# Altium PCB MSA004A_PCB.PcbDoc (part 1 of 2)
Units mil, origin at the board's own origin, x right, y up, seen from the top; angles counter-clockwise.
Board outline 2300 x 2720 mil, 2 copper layers (Top Layer, Bottom Layer), stack 62 mil thick; 117 components, 85 nets, 350 pads, 179 vias.
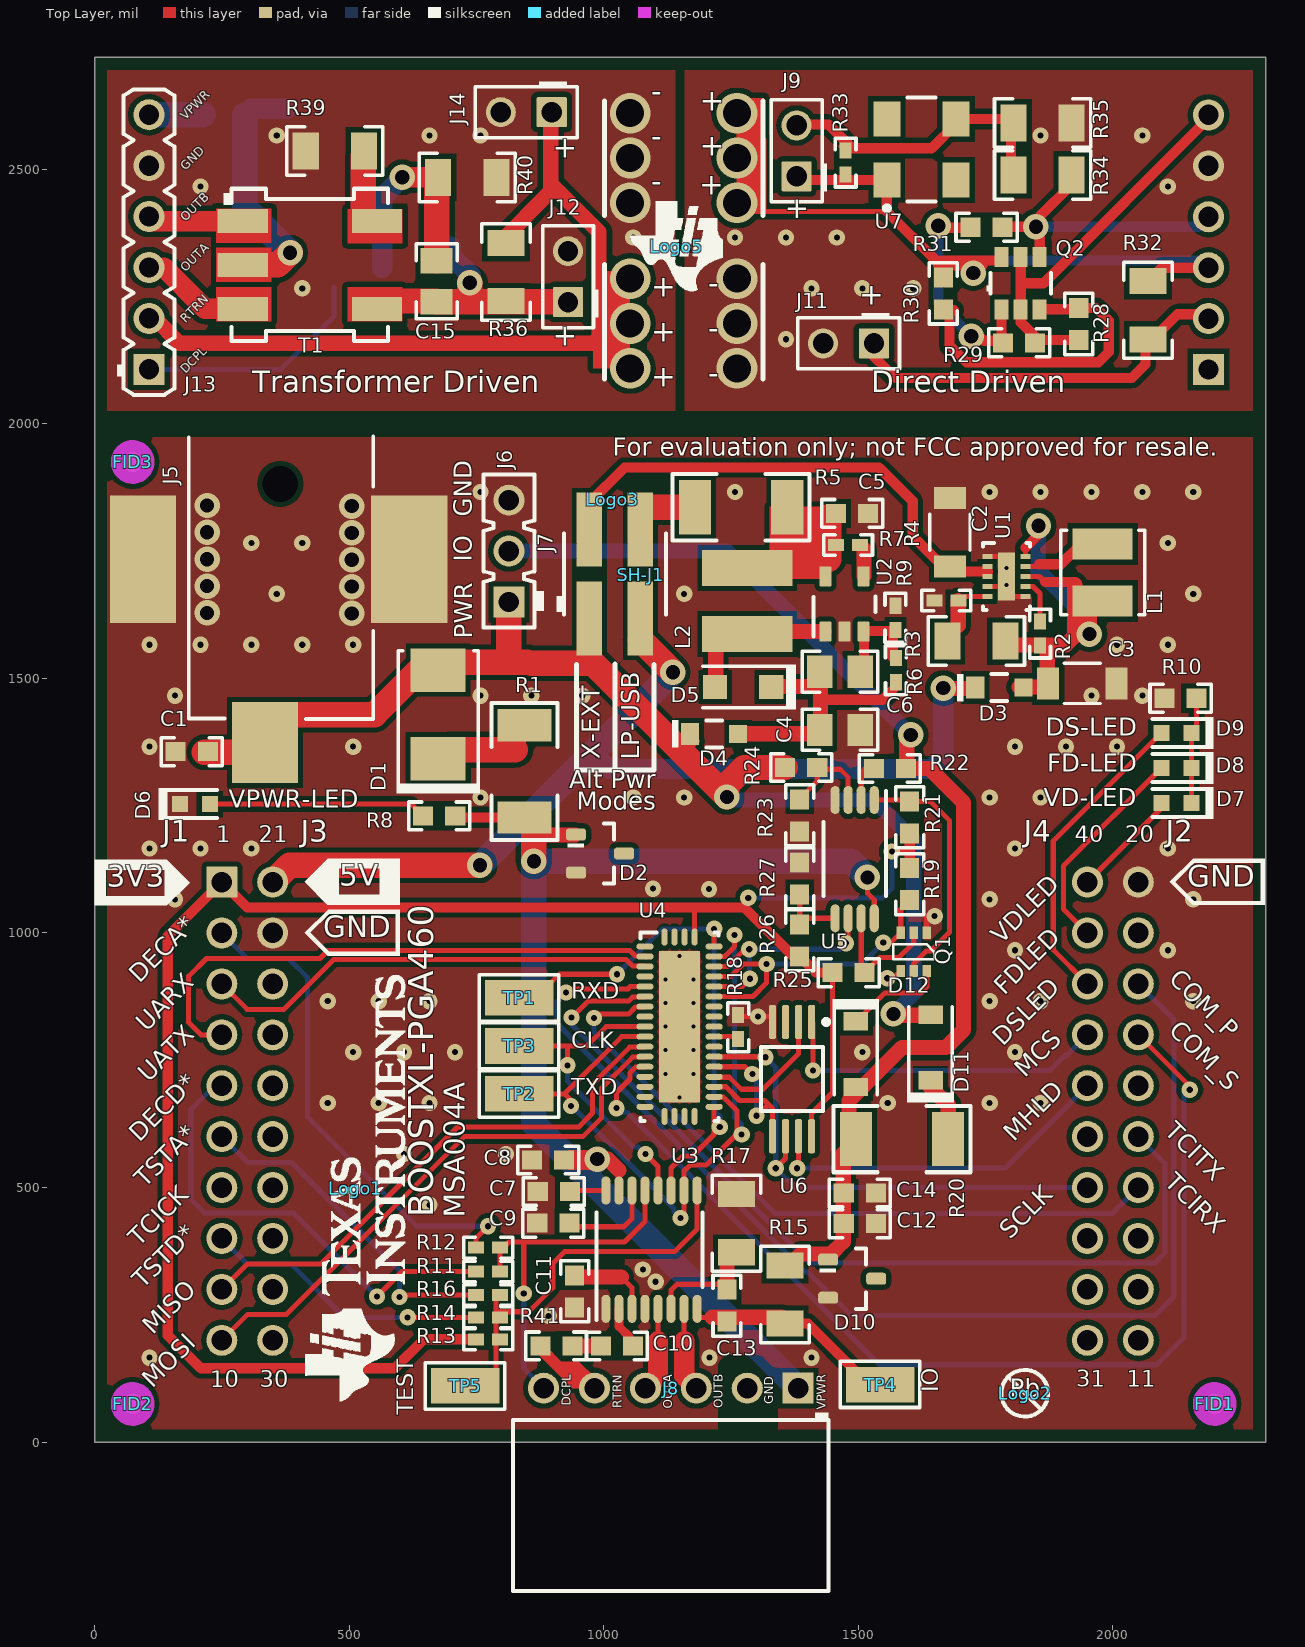
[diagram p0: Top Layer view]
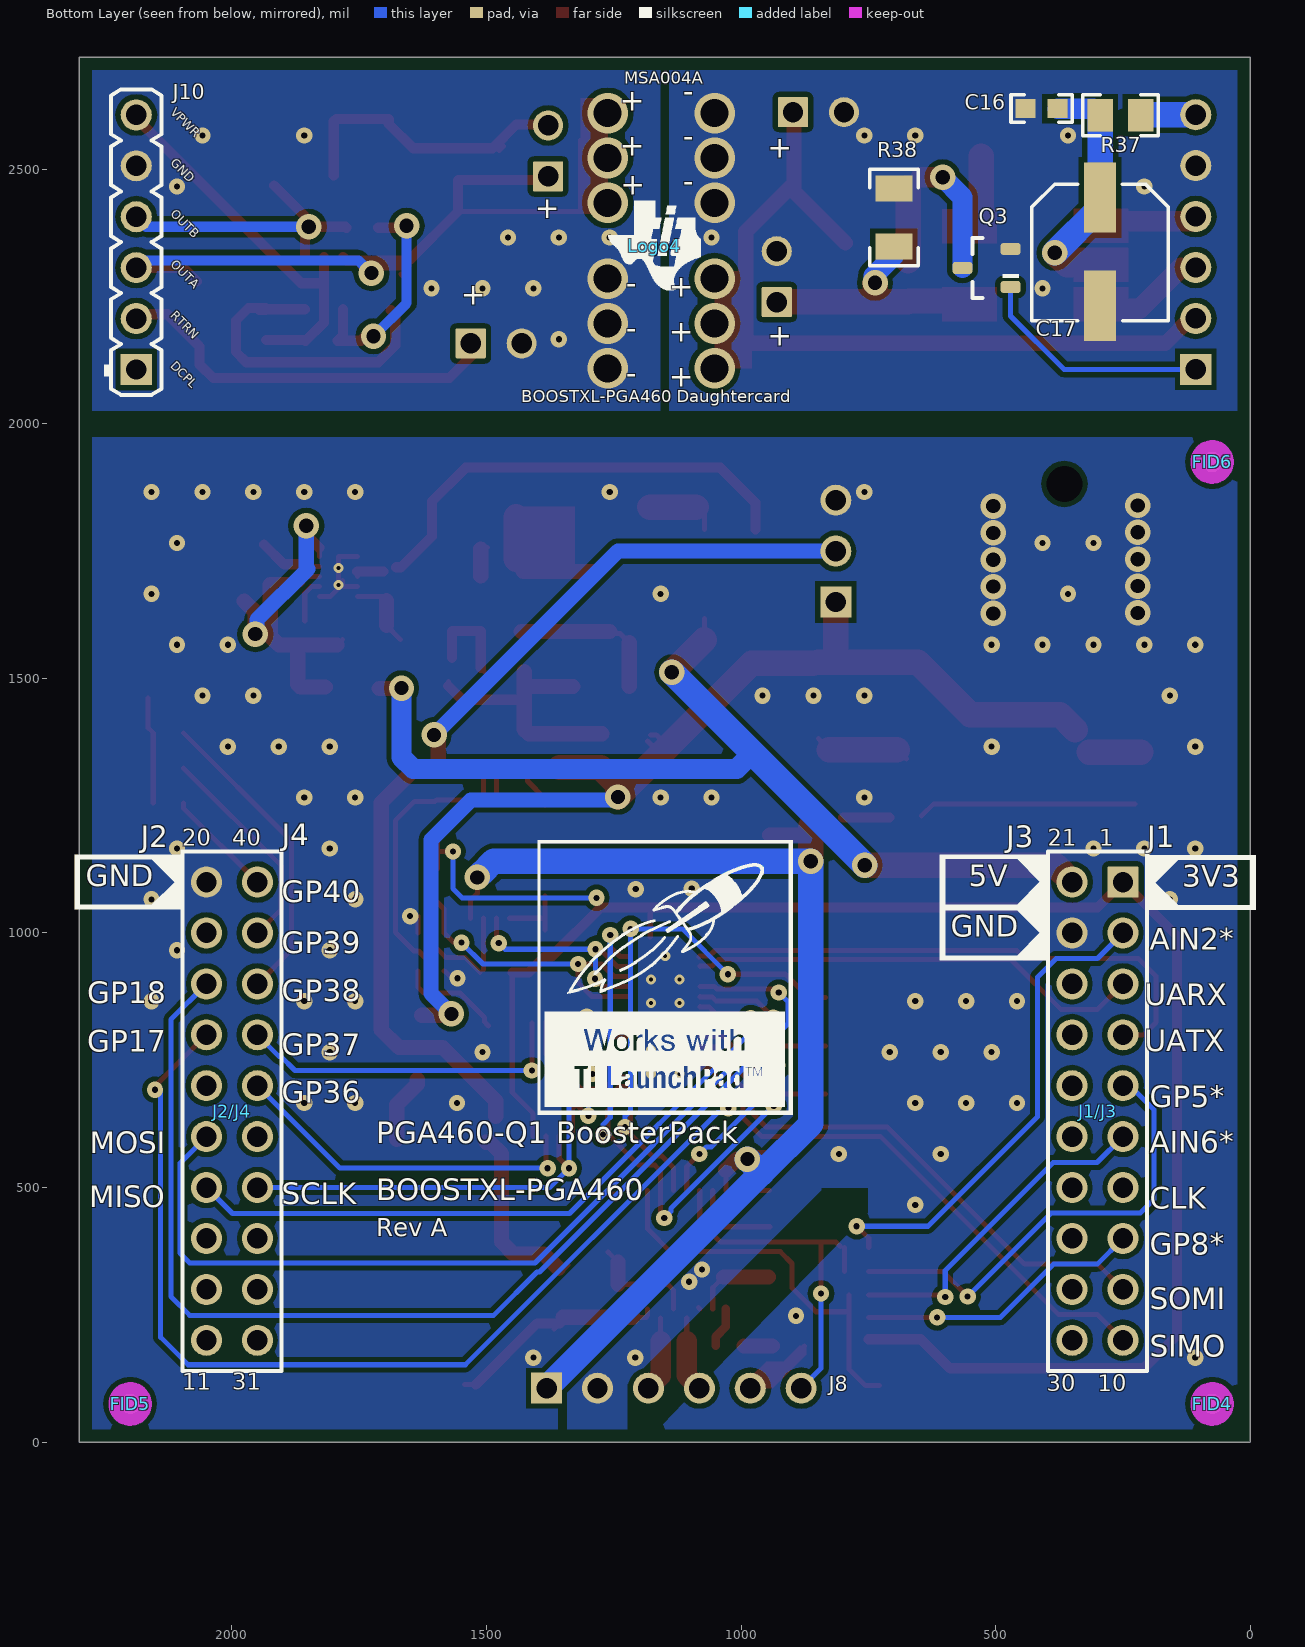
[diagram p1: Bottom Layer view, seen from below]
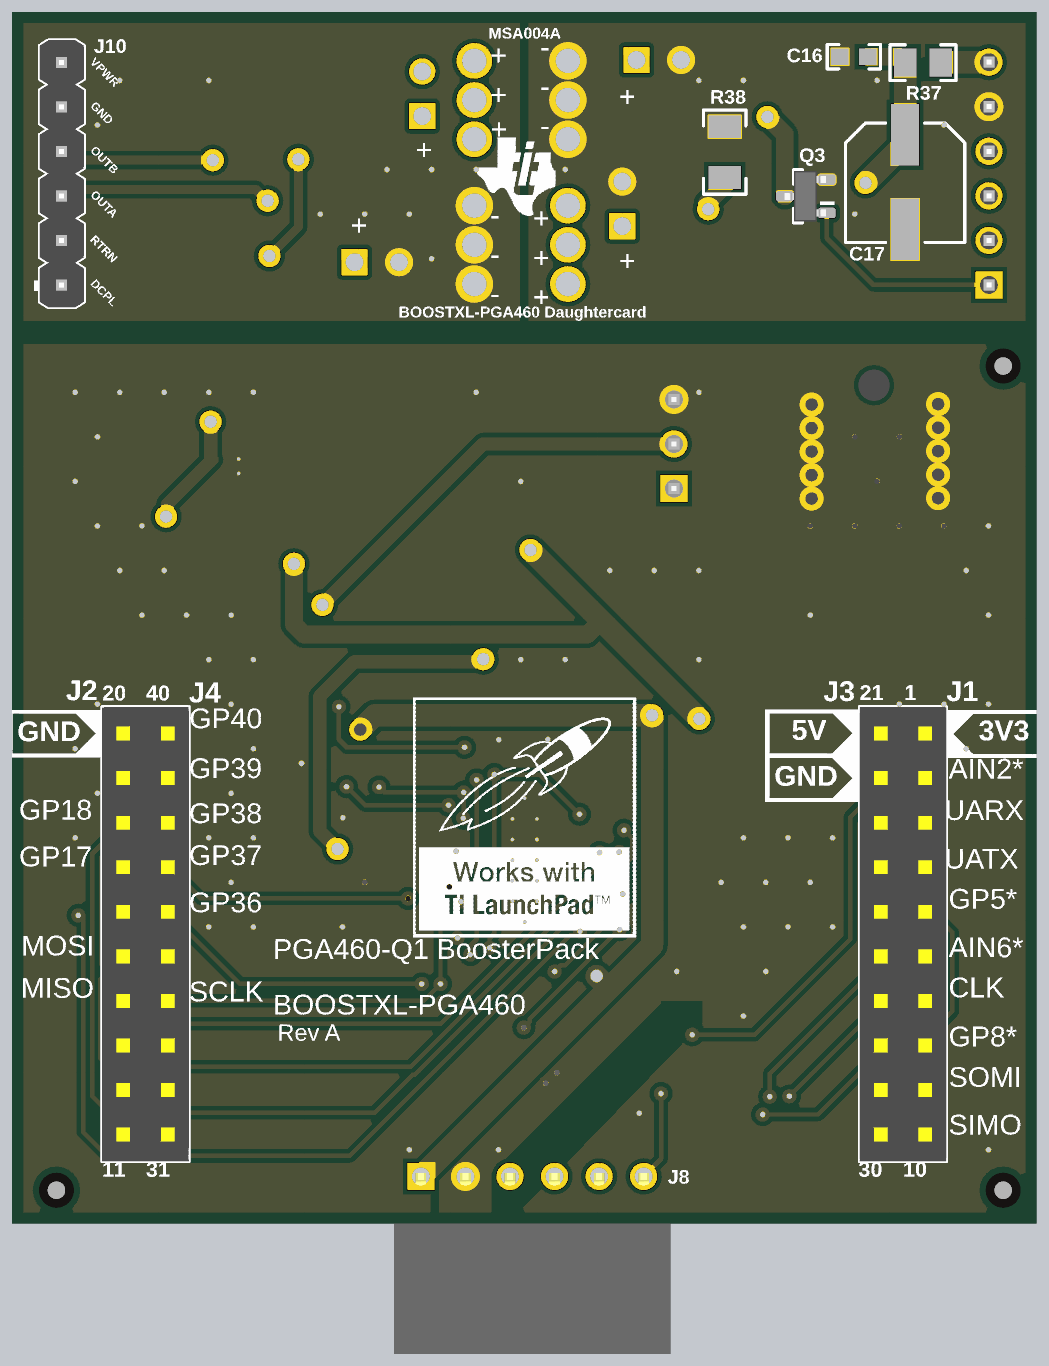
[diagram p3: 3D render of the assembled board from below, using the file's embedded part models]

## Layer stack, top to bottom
Top Solder: solder mask 0.4, Solder Resist, Dk 3.5
Top Layer: signal copper 1.4
Dielectric1: core 59.2, FR-4, Dk 4.8
Bottom Layer: signal copper 1.4
Bottom Solder: solder mask 0.4, Solder Resist, Dk 3.5

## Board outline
0,0 2300,0 2300,2720 0,2720
board region "Layer Stack Region 1": 0,2000 0,2720 2300,2720 2300,2000
board region "Layer Stack Region 1": 2300,2000 2300,0 0,0 0,2000

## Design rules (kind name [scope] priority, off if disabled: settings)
AcuteAngle [All] p1: minimum=4.50000000000000E+0001 checktracksonly=FALSE
AssemblyTestPointUsage [All] p1: valid=2
BoardOutlineClearance BoardOutlineClearance_MountingHoles [OnCopper and InComponentClass('Mounting Holes')] p1: gap=25
BoardOutlineClearance BoardOutlineClearance_Poly [OnCopper and IsPoly] p2: gap=25
BoardOutlineClearance [OnCopper and Not InComponentClass('Logo') and not InComponentClass('FiducialMark') and not InRegion(1000,500,4000,800) and not InPoly] p3: gap=25
Clearance Clearance_6 [InNamedPolygon('Top-GNDD')] p1: gap=10
Clearance Clearance_5 [InNamedPolygon('Btm-GNDX')] p2: gap=10
Clearance Clearance_4 [InNamedPolygon('Top-GNDX')] p3: gap=10
Clearance Clearance_3 [InNamedPolygon('Btm-GNDD')] p4: gap=10
Clearance Clearance_2 [InNamedPolygon('Top-GND')] p5: gap=10
Clearance Clearance_1 [InNamedPolygon('Btm-GND')] p6: gap=10
Clearance Clearance_Keepouts [((IsTrack Or IsArc) And Not InPoly) And IsFree and IsKeepOut vs ((IsTrack Or IsArc) And Not InPoly) And IsFree and IsKeepOut] p7: gap=0
Clearance Clearance_Poly [InPolygon] p8: gap=25
Clearance [All] p9: gap=7.87
ComponentClearance ComponentClearance_1 [All] p1: gap=10 collisioncheckmode=3 verticalgap=10 showdistances=FALSE
ComponentClearance ComponentClearance_MountingHoles_FiducialMarks [InComponentClass('Mounting Holes') vs InComponentClass('FiducialMark')] p2: gap=50 collisioncheckmode=3 verticalgap=10 showdistances=FALSE
ComponentClearance ComponentClearance_Shunt [InComponentClass('Header') vs InComponentClass('Shunt');] p3: gap=0 collisioncheckmode=3 verticalgap=0 showdistances=FALSE
ComponentClearance ComponentClearance_Logo [InComponentClass('Logo')] p4: gap=50 collisioncheckmode=3 verticalgap=10 showdistances=FALSE
ComponentClearance ComponentClearance_ScrewToNut [(HasFootprint('NY PMS 440 0025 PH')) vs (HasFootprint('Keystone_1902C'))] p5: gap=5 collisioncheckmode=3 verticalgap=10 showdistances=FALSE
ComponentClearance ComponentClearance_MountingHoles [InComponentClass('Mounting Holes')] p6: gap=250 collisioncheckmode=3 verticalgap=100000 showdistances=FALSE
ComponentClearance ComponentClearance_SmallPassives [HasFootprint('0201*') or HasFootprint('0402*') or HasFootprint('0508') or HasFootprint('0603*') or HasFootprint('0612') or HasFootprint('0805*') or HasFootprint('0815*') or HasFootprint('0830*') or HasFootprint('1206*') or HasFootprint('1210*') or HasFootprint('1808*') or HasFootprint('1812*') or HasFootprint('1825*') or HasFootprint('2010*') or HasFootprint('2220*') or HasFootprint('2225*') or HasFootprint('2512*') or HasFootprint('2728*') or HasFootprint('3518*') vs HasFootprint('0201*') or HasFootprint('0402*') or HasFootprint('0508') or HasFootprint('0603*') or HasFootprint('0612') or HasFootprint('0805*') or HasFootprint('0815*') or HasFootprint('0830*') or HasFootprint('1206*') or HasFootprint('1210*') or HasFootprint('1808*') or HasFootprint('1812*') or HasFootprint('1825*') or HasFootprint('2010*') or HasFootprint('2220*') or HasFootprint('2225*') or HasFootprint('2512*') or HasFootprint('2728*') or HasFootprint('3518*')] p7: gap=14.96 collisioncheckmode=3 verticalgap=10 showdistances=FALSE
ComponentClearance ComponentClearance_THtoSMT [IsThruComponent vs IsSMTComponent] p8: gap=40 collisioncheckmode=3 verticalgap=30 showdistances=FALSE
ComponentClearance ComponentClearance_THtoTH [IsThruComponent vs IsThruComponent] p9: gap=30 collisioncheckmode=3 verticalgap=30 showdistances=FALSE
DiffPairsRouting [All] p1: maxlimit=100 minlimit=10 mostfreqgap=10 toplayer_minwidth=15 toplayer_maxwidth=15 toplayer_prefwidth=15 bottomlayer_minwidth=15 bottomlayer_maxwidth=15 bottomlayer_prefwidth=15 maxuncoupledlength=1000
FabricationTestPointUsage TestPointUsage [All] p1: valid=2 allowmultiple=FALSE
FabricationTestpoint Testpoint [All] p1: side=3 testpointundercomponent=TRUE minsize=40 maxsize=100 preferedsize=60 minholesize=0 maxholesize=40 preferedholesize=32 testpointgrid=1 allowsidetop=TRUE allowsidebottom=TRUE usegrid=TRUE gridtolerance=0.01
FanoutControl Fanout_LCC [IsLCC] p1: bgadir=Out bgaviamode=Centered fanoutstyle=Auto fanoutdirection=Alternating viagrid=1 // Fanout_LCC (Default Rule)
FanoutControl Fanout_BGA [IsBGA] p2: bgadir=Out bgaviamode=Centered fanoutstyle=Auto fanoutdirection=Alternating viagrid=1 // Fanout_BGA (Default Rule)
FanoutControl Fanout_Default [All] p4: bgadir=Out bgaviamode=Centered fanoutstyle=Auto fanoutdirection=Alternating viagrid=1 // Fanout_Default (Default Rule)
FanoutControl Fanout_Small [(CompPinCount < 5)] p5: bgadir=Out bgaviamode=Centered fanoutstyle=Auto fanoutdirection=OutThenIn viagrid=1 // Fanout_Small (Default Rule)
HoleSize [All] p1: absolutevalues=TRUE maxlimit=251 minlimit=7.87 maxpercent=80.000 minpercent=20.000
MinimumAnnularRing MinimumAnnularRing_ThermalPadVias [IsVia and InAnyComponent] p1: minimumring=5.91
MinimumAnnularRing [All] p2: minimumring=8
MinimumSolderMaskSliver MinimumSolderMaskSliver_Logo [InComponentClass('Logo') vs InComponentClass('Logo')] p1: minsoldermaskwidth=0.7
MinimumSolderMaskSliver [All] p2: minsoldermaskwidth=3.94
PlaneConnect [All] p1: planeconnectstyle=Relief reliefexpansion=10 reliefentries=4 reliefconductorwidth=10 reliefairgap=10
PolygonConnect PolygonConnect_6 [All vs IsNamedPolygon('Top-GNDD')] p1: connectstyle=Direct reliefconductorwidth=10 reliefentries=4 polygonreliefangle="90 Angle" airgapwidth=10
PolygonConnect PolygonConnect_5 [All vs IsNamedPolygon('Top-GNDX')] p2: connectstyle=Direct reliefconductorwidth=10 reliefentries=4 polygonreliefangle="90 Angle" airgapwidth=10
PolygonConnect PolygonConnect_4 [All vs IsNamedPolygon('Btm-GNDD')] p3: connectstyle=Direct reliefconductorwidth=10 reliefentries=4 polygonreliefangle="90 Angle" airgapwidth=10
PolygonConnect PolygonConnect_3 [All vs IsNamedPolygon('Btm-GNDX')] p4: connectstyle=Direct reliefconductorwidth=10 reliefentries=4 polygonreliefangle="90 Angle" airgapwidth=10
PolygonConnect PolygonConnect_2 [All vs IsNamedPolygon('Btm-GND')] p5: connectstyle=Direct reliefconductorwidth=10 reliefentries=4 polygonreliefangle="90 Angle" airgapwidth=10
PolygonConnect PolygonConnect_1 [All vs IsNamedPolygon('Top-GND')] p6: connectstyle=Direct reliefconductorwidth=10 reliefentries=4 polygonreliefangle="90 Angle" airgapwidth=10
PolygonConnect [All] p7: connectstyle=Relief reliefconductorwidth=10 reliefentries=4 polygonreliefangle="90 Angle" airgapwidth=10
RoutingVias ThermalPadVias [IsVia and InAnyComponent] p1: holewidth=7.87 width=19.68 viastyle="Through Hole" minholewidth=7.87 minwidth=19.68 maxholewidth=12.99 maxwidth=23.62
RoutingVias [All] p2: holewidth=16 width=34 viastyle="Through Hole" minholewidth=7.87 minwidth=26 maxholewidth=40 maxwidth=65
SilkToBoardRegionClearance [Not ((IsComment or IsDesignator) And (Hide <> 'False')) and not InRegion(1000,500,4000,800)] p1:
SilkToSilkClearance SilkToSilkClearance_Pb-FreeLogo [(HasFootprint('Pb-Free_Overlay_Medium') OR HasFootprint('Pb-Free_Overlay_Small')) vs (HasFootprint('Pb-Free_Overlay_Medium') OR HasFootprint('Pb-Free_Overlay_Small'))] p1: silktosilkclearance=0
SilkToSilkClearance [All] p2: silktosilkclearance=4
SilkToSolderMaskClearance SilkToComponentPadClearance [IsPad and InAnycomponent] p1: minsilkscreentomaskgap=5 clearancetoexposedcopper=TRUE
SilkToSolderMaskClearance "Silk to Solder Mask Opening" [All] p2: minsilkscreentomaskgap=4 clearancetoexposedcopper=FALSE
SolderMaskExpansion [All] p1: expansion=1.97
Width [All] p1: maxlimit=100 minlimit=6 preferedwidth=10 checkconnectedcopper=TRUE
15 further rules are at their usual default settings.

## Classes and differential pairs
component class Logo: Logo1 Logo4 Logo5
component class MSA004A_HW: FID1 FID2 FID3 FID4 FID5 FID6 Logo1 Logo2 Logo3 Logo4 Logo5 SH-J1 ZZ1 ZZ2 ZZ3 ZZ4 ZZ5
component class FiducialMark: FID1 FID2 FID3 FID4 FID5 FID6
component class AssemblyNote: ZZ1 ZZ2 ZZ3 ZZ4 ZZ5
component class Header: J6 J7 J9 J10 J11 J12 J13 J14
component class MSA004A_USSC: C7 C8 C9 C10 C11 C12 C13 C14 D10 D11 D12 J1/J3 J2/J4 J8 Q1 R11 R12 R13 R14 R15 R16 R17 R18 R19 R20 R21 R22 R23 R24 R25 R26 R27 R41 TP1 TP2 TP3 TP4 TP5 U3 U4 U5 U6
component class MSA004A_XDCR: C15 C16 C17 H1 J9 J10 J11 J12 J13 J14 Q2 Q3 R28 R29 R30 R31 R32 R33 R34 R35 R36 R37 R38 R39 R40 T1 U7
component class MSA004A_PWR: C1 C2 C3 C4 C5 C6 D1 D2 D3 D4 D5 D6 D7 D8 D9 J5 J6 J7 L1 L2 R1 R2 R3 R4 R5 R6 R7 R8 R9 R10 U1 U2

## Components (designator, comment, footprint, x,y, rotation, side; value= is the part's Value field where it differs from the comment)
C1 "C1608X5R1H474K080AB" 0603 191,1356 r180 top
C2 "GRM31CR71H225KA88L" 1206_180 1680,1787 r90 top
C3 "GRM31CR61A226KE19L" 1206_180 1940,1490 r0 top
C4 "GRM21BR61C106KE15L" 0805_HV 1464,1399 r0 top
C5 "GRM188R61A475MAAJ" 0603 1488,1824 r0 top
C6 "CC0805KRX7R9BB102" 0805_HV 1464,1513 r0 top
C7 "C1608X7R1H104K080AA" 0603 902,492 r180 top
C8 "C1608X7R1H104K080AA" 0603 891,554 r180 top
C9 "C1608X7R1H104K080AA" 0603 901,430 r180 top
C10 "GRM1885C2A391JA01D" 0603 1026,189 r180 top
C11 "GRM188R71H333KA61D" 0603 943,296 r270 top
C12 "C1608X7R1H104K080AA" 0603 1503,429 r0 top
C13 "C1608X7R1H104K080AA" 0603 1242,268 r90 top
C14 "C0603C221K5RACTU" 0603 1503,489 r0 top
C15 "GRM2165C2A152JA01D" 0805_HV 672,2280 r90 top
C16 "C1608X7R1H104K080AA" 0603 410,2619 r180 bottom
C17 "EMVA350ADA101MF80G" CAPSMT_62_F80 295,2338 r270 bottom
D1 "B260-13-F" SMB 675,1429 r90 top
D2 "SZMMBZ27VCLT1G" SOT-23 993,1156 r0 top
D3 "DB2130200L" SMini2-F5-B 1777,1482 r0 top
D4 "DB2130200L" SMini2-F5-B 1217,1391 r0 top
D5 "PMEG6010CEH,115" SOD-123F 1274,1483 r180 top
D6 "LTST-C191KFKT" LTST-C191_Orange 197,1253 r180 top
D7 "LTST-C191KRKT" LTST-C191_Red 2125,1255 r0 top
D8 "LTST-C191KRKT" LTST-C191_Red 2125,1324 r0 top
D9 "LTST-C191KRKT" LTST-C191_Red 2125.03,1392.97 r0 top
D10 "SZMMBZ27VCLT1G" SOT-23 1488,321 r0 top
D11 "BAV3004W-7-F" SOD-123 1642,775 r90 top
D12 "BAV3004W-7-F" SOD-123 1495,762 r270 top
FID1 "Fiducial" Fiducial10-20 2200,75 r0 top
FID2 "Fiducial" Fiducial10-20 75,75 r0 top
FID3 "Fiducial" Fiducial10-20 75,1925 r0 top
FID4 "Fiducial" Fiducial10-20 75,75 r180 bottom
FID5 "Fiducial" Fiducial10-20 2200,75 r180 bottom
FID6 "Fiducial" Fiducial10-20 75,1925 r180 bottom
J1/J3 "SSQ-110-03-T-D" BoosterPack_40pin_J1J3 300,650 r180 bottom locked
J2/J4 "SSQ-110-03-T-D" BoosterPack_40pin_J2J4 2000,650 r180 bottom locked
J5 "RASM712PX" Switchcraft_RASM712PX 365,2000 r180 top
J6 "TSW-103-07-T-S" Samtec_TSW-103-07-T-S 814,1750 r90 top
J7 "0015912040" Molex_0015912040 1022,1705 r90 top
J8 "PPPC061LGBN-RC" Sullins_xPxC061LGBN 1132,106 r270 top
J9 "PEC02SAAN" CONN_PEC02SAAN 1379,2536 r90 top
J10 "PBC06SAAN" Sullins_PxC06SAAN 2187.95,2356.62 r90 bottom
J11 "PEC02SAAN" CONN_PEC02SAAN 1481,2158 r180 top
J12 "PEC02SAAN" CONN_PEC02SAAN 930,2289 r90 top
J13 "PBC06SAAN" Sullins_PxC06SAAN 107.05,2357 r90 top
J14 "PEC02SAAN" CONN_PEC02SAAN 848,2612 r180 top
L1 "LQH44PN100MP0L" IND_LQH44P 1980,1708 r270 top
L2 "SDR0403-100ML" SDR0403 1282,1652 r270 top
Logo1 "Texas Instruments" TI_Stacked_Overlay_Small 512,499 r90 top
Logo2 "Pb-Free Symbol" Pb-Free_Overlay_Small 1827,96 r0 top
Logo3 "FCC disclaimer" FCC_disclaimer 1017,1852 r0 top
Logo4 "Texas Instruments" TI_Symbol_Overlay_Small 1170.12,2349.78 r180 bottom
Logo5 "Texas Instruments" TI_Symbol_Overlay_Small 1142.74,2348.5 r0 top
Q1 "2N7002DW" SOT-363 1609,963 r270 top
Q2 "FDC6506P" superSOT-6 1819,2276 r90 top
Q3 "BSS123" SOT-23 518,2306 r0 bottom
R1 "CRCW201010R0JNEF" 2010 844.56,1317.46 r270 top
R2 "CRCW0402100KFKED" 0402 1857,1588 r90 top
R3 "RC1206FR-072M2L" 1206 1732,1573 r0 top
R4 "CRCW0402383KFKED" 0402 1673,1653 r180 top
R5 "CRCW201033R0JNEF" 2010 1270,1836 r0 top
R6 "CRCW040251K1FKED" 0402 1574,1516 r270 top
R7 "CRCW040210K0FKED" 0402 1480,1762 r0 top
R8 "RC0603JR-0751KL" 0603 677,1230 r180 top
R9 "CRCW040210K0FKED" 0402 1573,1619 r90 top
R10 "RC0603JR-0710KL" 0603 2133,1461 r180 top
R11 "CRCW04020000Z0ED" 0402 773,335 r180 top
R12 "CRCW04020000Z0ED" 0402 773,382 r180 top
R13 "CRCW0402100KJNED" 0402 773,201.79 r180 top
R14 "CRCW04020000Z0ED" 0402 773,245 r180 top
R15 "CRCW12060000Z0EA" 1206 1356,290 r270 top
R16 "CRCW04020000Z0ED" 0402 773,289 r180 top
R17 "CRCW12060000Z0EA" 1206 1261,430 r270 top
R18 "CRCW040210K0FKED" 0402 1264,815 r90 top
R19 "CRCW06031K00JNEA" 0603 1601,1096 r270 top
R20 "CRCW20101K00JNEF" 2010 1586,595 r0 top
R21 "CRCW06031K00JNEA" 0603 1601,1227 r270 top
R22 "CRCW0603100KJNEA" 0603 1562,1323 r0 top
R23 "CRCW0603100KJNEA" 0603 1385,1231 r90 top
R24 "CRCW0603100KJNEA" 0603 1388,1325 r180 top
R25 "CRCW06031K00JNEA" 0603 1481,922 r180 top
R26 "CRCW0603100KJNEA" 0603 1385,985.5 r90 top
R27 "CRCW0603100KJNEA" 0603 1385,1107 r270 top
R28 "CRCW06031K00JNEA" 0603 1933,2196 r270 top
R29 "CRCW06031K00JNEA" 0603 1816,2159 r0 top
R30 "CRCW06031K00JNEA" 0603 1667,2256 r90 top
R31 "CRCW06031K00JNEA" 0603 1752,2386 r0 top
R32 "CRCW12060000Z0EA" 1206 2069,2223 r270 top
R33 "CRCW04022K00JNED" 0402 1475,2513 r270 top
R34 "CRCW12060000Z0EA" 1206 1862,2489 r180 top
R35 "CRCW12060000Z0EA" 1206 1862,2591 r180 top
R36 "CRCW12060000Z0EA" 1206 808,2298 r90 top
R37 "CRCW0805100RJNEA" 0805_HV 255,2606 r0 bottom
R38 "CRCW12062K70JNEA" 1206 700,2405 r270 bottom
R39 "CRCW12060000Z0EA" 1206 472,2536 r0 top
R40 "CRCW12060000Z0EA" 1206 732,2484 r180 top
R41 "CRCW0603100RFKEA" 0603 907,189 r0 top
SH-J1 "60900213421" Wurth_60900213421 1073,1704 r90 top
T1 "B78416A2232A003" TDK_B78416A2232A003 423,2312 r0 top
TP1 "RXD" Testpoint_Keystone_Miniature 834,873 r0 top
TP2 "TXD" Testpoint_Keystone_Miniature 834,684 r0 top
TP3 "CLK" Testpoint_Keystone_Miniature 834,778 r180 top
TP4 "IO" Testpoint_Keystone_Miniature 1543,113 r180 top
TP5 "TEST" Testpoint_Keystone_Miniature 728,111 r0 top
U1 "TPS62175DQCR" DQC0010A 1791,1700 r0 top
U2 "LMR62421XMFX/NOPB" DBV0005A_N 1473,1646 r90 top
U3 "PGA460TPWRQ1" PW0016A_N 1094,378 r90 top
U4 "TS3L501ERUAR" RUA0042A 1149,816 r0 top
U5 "LM2903PW" PW0008A_N 1493,1145 r270 top
U6 "23LC512-I/ST" TSSOP-8 1370,713 r270 top
U7 "MA40H1S-R" MA40H1S 1624,2538.62 r90 top
ZZ1 "These assemblies are ESD sensitive, ESD precautions shall be observed." AssemblyNote 185,3829.11 r0 top
ZZ2 "These assemblies must be clean and free from flux and all contaminants. Use of no clean flux is not acceptable." AssemblyNote 185,3740.56 r0 top
ZZ3 "These assemblies must comply with workmanship standards IPC-A-610 Class 2, unless otherwise specified." AssemblyNote 185,3652 r0 top
ZZ4 "Add score line between boards for separation post-assembly." AssemblyNote 185,3528 r0 top
ZZ5 "Connect MA58MF14-7N (H1) XDCR to J12 holes. Black wired pin must be connected to GND_XD (-)." AssemblyNote 185,3448 r0 top

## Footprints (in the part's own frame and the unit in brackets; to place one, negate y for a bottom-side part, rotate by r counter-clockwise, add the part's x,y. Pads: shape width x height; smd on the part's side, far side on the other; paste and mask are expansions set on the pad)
0402 [mm] "0402 from SM-752 data"
  rect 0.8x0.6 smd: 1(-0.6,0) 2(0.6,0)
  silkscreen extent -1.22,-0.52 1.22,0.52, body extent -0.55,-0.3 0.55,0.3, height 0.6
0603 [mm] "0603 from SM-752 data"
  rect 1x0.95 smd: 1(-0.8,0) 2(0.8,0)
  silkscreen extent -1.52,-0.69 1.52,0.69, body extent -0.87,-0.47 0.87,0.47, height 1
0805_HV [mil] "0805 with 30mil clearance between pads"
  rect 50x63 smd: 1(-40,0) 2(40,0)
  silkscreen extent -74,-40 74,40, body extent -43,-29 43,29, height 57
1206 [mm] "1206 from SM-752 data"
  rect 1.3x1.85 smd: 1(-1.45,0) 2(1.45,0)
  silkscreen extent -2.4,-1.21 2.4,1.21, body extent -1.7,-0.9 1.7,0.9, height 1.35
1206_180 [mm] "1206_180"
  rect 1.1x1.6 smd: 1(-1.7,0) 2(1.7,0)
  silkscreen extent -0.9,-1 0.9,1, body extent -1.75,-0.95 1.75,0.95, height 1.8
2010 [mm] "Chip Capacitor, Body 5.08x2.54mm, IPC Medium Density"
  rect 1.6x2.7 smd: 1(-2.3,0) 2(2.3,0)
  silkscreen extent -3.42,-1.65 3.42,1.65, body extent -2.73,-1.45 2.73,1.45, height 1.66
AssemblyNote [mil] "Assembly Note"
BoosterPack_40pin_J1J3 [mm] "Receptacle, 2.54mm, 10x2, TH"
  rrect6% 1.55x1.55 hole 1.02: 1(1.27,11.43)
  round 1.55 hole 1.02: 2(1.27,8.89) 3(1.27,6.35) 4(1.27,3.81) 5(1.27,1.27) 6(1.27,-1.27) 7(1.27,-3.81) 8(1.27,-6.35) 9(1.27,-8.89) 10(1.27,-11.43) 21(-1.27,11.43) 22(-1.27,8.89) 23(-1.27,6.35) 24(-1.27,3.81) 25(-1.27,1.27) 26(-1.27,-1.27) 27(-1.27,-3.81) 28(-1.27,-6.35) 29(-1.27,-8.89) 30(-1.27,-11.43)
  silkscreen extent -2.48,-12.95 2.48,12.95, body extent -2.48,-12.95 2.48,12.95, height 8.51
BoosterPack_40pin_J2J4 [mm] "Receptacle, 2.54mm, 10x2, TH"
  round 1.55 hole 1.02: 11(-1.27,-11.43) 12(-1.27,-8.89) 13(-1.27,-6.35) 14(-1.27,-3.81) 15(-1.27,-1.27) 16(-1.27,1.27) 17(-1.27,3.81) 18(-1.27,6.35) 19(-1.27,8.89) 20(-1.27,11.43) 31(1.27,-11.43) 32(1.27,-8.89) 33(1.27,-6.35) 34(1.27,-3.81) 35(1.27,-1.27) 36(1.27,1.27) 37(1.27,3.81) 38(1.27,6.35) 39(1.27,8.89) 40(1.27,11.43)
  silkscreen extent -2.48,-12.95 2.48,12.95, body extent -2.48,-12.95 2.48,12.95, height 8.51
CAPSMT_62_F80 [mm] "6.3 x 7.7mm:  Chemi-Con F80"
  rect 3.5x1.6 smd: 1(-2.7,0) 2(2.7,0)
  silkscreen extent -3.36,-3.4 3.44,3.4, body extent -3.4,-3.4 3.44,3.4, height 8
CONN_PEC02SAAN [mm] "SULLINS"
  rrect7% 1.5x1.5 hole 1.016: 1(-1.27,0)
  round 1.5 hole 1.016: 2(1.27,0)
  silkscreen extent -2.54,-1.52 2.54,1.27, body extent -2.54,-1.27 2.54,1.27, height 8.38
DBV0005A_N [mm] "SOT23, 5-Leads, Body 2.9x1.6mm, Pitch 0.95mm, Lead Span 2.8mm, IPC Medium Density"
  rrect17% 1x0.6 smd: 1(-1.375,0.95) 2(-1.375,0) 3(-1.375,-0.95) 4(1.375,-0.95) 5(1.375,0.95)
  silkscreen extent -1.62,-1.55 0.38,1.55, body extent -1.42,-1.46 1.42,1.46, height 1.09
DQC0010A [mm] "SON, 10-Leads, Body 2x3mm, Pitch 0.5mm, Thermal Pad 2.4x0.84mm"
  rect 0.5x0.25 smd: 1(-0.95,1) 2(-0.95,0.5) 3(-0.95,0) 4(-0.95,-0.5) 5(-0.95,-1) 6(0.95,-1) 7(0.95,-0.5) 8(0.95,0) 9(0.95,0.5) 10(0.95,1)
  rect 0.84x2.4 smd paste-0.42: 11(0,0)
  silkscreen extent -1.18,-1.67 1.18,1.67, body extent -1.05,-1.55 1.05,1.55, height 0.81
FCC_disclaimer [mil]
Fiducial10-20 [mm]
  round 1 smd mask+0.5: 1(0,0)
  Top Layer keep-out circle w1.178: c0,0 r0.5
IND_LQH44P [mm] "Murata"
  rect 1.55x3 smd: 1(-1.425,0) 2(1.425,0)
  silkscreen extent -2.1,-2.1 2.1,2.1, body extent -2.1,-2.1 2.1,2.1, height 1.8
LTST-C191_Orange [mm] "SMD, 2-Leads, Body 1.6x0.8mm"
  rect 0.8x0.8 smd: 1(-0.75,0) 2(0.75,0)
  silkscreen extent -1.1,-0.8 1.8,0.8, body extent -0.85,-0.45 0.85,0.45, height 0.65
LTST-C191_Red [mm] "SMD, 2-Leads, Body1.6x0.8mm"
  rect 0.8x0.8 smd: 1(-0.75,0) 2(0.75,0)
  silkscreen extent -1.2,-0.8 1.85,0.8, body extent -0.85,-0.45 0.85,0.45, height 0.66
MA40H1S [mm] "SMD, 4-Leads, Body 5.3x5.3mm"
  rect 1.75x1.35 smd: 1(-1.525,1.725) 2(-1.525,-1.725) 3(1.525,-1.725) 4(1.525,1.725)
  silkscreen extent -3.05,-0.7 2.6,1.85, body extent -2.6,-2.6 2.6,2.6, height 1.25
Molex_0015912040 [mm] "Header, 2.54mm, 2x2, Gold, SMT"
  rect 3.68x1.27 smd: 1(-2.22,1.27) 2(2.22,1.27) 3(-2.22,-1.27) 4(2.22,-1.27)
  silkscreen extent -2.03,-2.54 2.03,2.9, body extent -3.49,-2.54 3.49,2.54, height 9.65
Pb-Free_Overlay_Small [mil]
  silkscreen extent -46,-46 46,46
PW0008A_N [mm] "TSOP, 8-Leads, Body 3x4.4mm, Pitch 0.65mm, IPC Medium Density"
  oval 1.4x0.45 smd: 1(-2.95,0.975) 2(-2.95,0.325) 3(-2.95,-0.325) 4(-2.95,-0.975) 5(2.95,-0.975) 6(2.95,-0.325) 7(2.95,0.325) 8(2.95,0.975)
  silkscreen extent -3.4,-1.55 1.85,1.55, body extent -3.21,-1.5 3.21,1.5, height 1.2
PW0016A_N [mm] "TSOP, 16-Leads, Body 5x4.4mm, Pitch 0.65mm, IPC Medium Density"
  oval 1.4x0.45 smd: 1(-2.95,2.275) 2(-2.95,1.625) 3(-2.95,0.975) 4(-2.95,0.325) 5(-2.95,-0.325) 6(-2.95,-0.975) 7(-2.95,-1.625) 8(-2.95,-2.275) 9(2.95,-2.275) 10(2.95,-1.625) 11(2.95,-0.975) 12(2.95,-0.325) 13(2.95,0.325) 14(2.95,0.975) 15(2.95,1.625) 16(2.95,2.275)
  silkscreen extent -3.5,-2.55 1.85,2.75, body extent -3.21,-2.5 3.21,2.5, height 1
RUA0042A [mm] "QFN, 42-Leads, Body 3.5x9mm, Pitch 0.5mm, Thermal Pad 2.05x7.55mm, TI Recommended"
  oval 0.85x0.3 smd: 1(-1.725,4) 2(-1.725,3.5) 3(-1.725,3) 4(-1.725,2.5) 5(-1.725,2) 6(-1.725,1.5) 7(-1.725,1) 8(-1.725,0.5) 9(-1.725,0) 10(-1.725,-0.5) 11(-1.725,-1) 12(-1.725,-1.5) 13(-1.725,-2) 14(-1.725,-2.5) 15(-1.725,-3) 16(-1.725,-3.5) 17(-1.725,-4) 22(1.725,-4) 23(1.725,-3.5) 24(1.725,-3) 25(1.725,-2.5) 26(1.725,-2) 27(1.725,-1.5) 28(1.725,-1) 29(1.725,-0.5) 30(1.725,0) 31(1.725,0.5) 32(1.725,1) 33(1.725,1.5) 34(1.725,2) 35(1.725,2.5) 36(1.725,3) 37(1.725,3.5) 38(1.725,4)
  oval 0.3x0.85 smd: 18(-0.75,-4.475) 19(-0.25,-4.475) 20(0.25,-4.475) 21(0.75,-4.475) 39(0.75,4.475) 40(0.25,4.475) 41(-0.25,4.475) 42(-0.75,4.475)
  rect 2.05x7.55 smd paste-1.25: 43(0,0)
  silkscreen extent -1.95,-4.7 1.95,4.7, body extent -1.8,-4.55 1.8,4.55, height 0.81
Samtec_TSW-103-07-T-S [mm] "Header, 2.54 mm, 3x1, TH"
  rect 1.55x1.55 hole 1.02: 1(-2.54,0)
  round 1.55 hole 1.02: 2(0,0) 3(2.54,0)
  silkscreen extent -3.81,-1.75 3.81,1.27, body extent -3.81,-1.27 3.81,1.27, height 8.39
SDR0403 [mm] "BOURNS"
  rect 1.8x4.5 smd: 1(-1.65,0) 2(1.65,0)
  body extent -2.4,-2.4 2.4,2.4, height 3.3
SMB [mil] "Molded Diode, 2-Leads, Body 5.4x3.6mm, IPC Medium Density, based on OnSemi component dimensions"
  rect 85x107.99 smd: 1(-87.01,0) 2(87.01,0)
  silkscreen extent -155,-82 125,82, body extent -106,-71 106,71, height 91
SMini2-F5-B [mm] "Panasonic"
  rect 0.9x1.1 smd: 1(-1.2,0)
  rect 0.9x0.9 smd: 2(1.2,0)
  silkscreen extent -2.1,-0.67 0.38,0.67, body extent -0.9,-0.67 0.9,0.67, height 0.81
SOD-123 [mm] "On Semi recommended land pattern"
  rect 0.915x1.22 smd: 1(-1.637,0) 2(1.637,0)
  silkscreen extent -2.74,-1.17 2.03,1.17, body extent -1.93,-0.9 1.93,0.9, height 1.35
SOD-123F [mm] "NXP recommended land pattern"
  rect 1.2x1.2 smd paste-0.05: 1(-1.4,0) 2(1.4,0)
  silkscreen extent -2.64,-1.12 2.01,1.12, body extent -1.8,-0.85 1.8,0.85, height 1.2
SOT-23 [mm] "SOT23, 3-Leads, Body 2.9x1.3mm, Pitch 0.95mm, Lead Span 2.5mm, IPC Medium Density"
  rrect50% 1x0.6 smd: 1(-1.2,0.95) 2(-1.2,-0.95) 3(1.2,0)
  silkscreen extent -1.62,-1.5 0.7,1.5, body extent -1.16,-1.45 1.21,1.45, height 1
SOT-363 [mm]
  rect 0.6x0.42 smd mask+0.051: 1(-0.95,0.65) 2(-0.95,0) 3(-0.95,-0.65) 4(0.95,-0.65) 5(0.95,0) 6(0.95,0.65)
  silkscreen extent -0.38,-1.02 0.38,1.02, body extent -1.1,-1.1 1.1,1.1, height 1.12
Sullins_PxC06SAAN [mil] "Header, 2.54mm, 6x1, TH"
  rect 61.02x61.02 hole 40: 1(-250,0)
  round 61.02 hole 40: 2(-150,0) 3(-50,0) 4(50,0) 5(150,0) 6(250,0)
  silkscreen extent -300,-50 300,63, body extent -300,-50 300,50, height 330
Sullins_xPxC061LGBN [mm] "Receptacle, 2.54mm, 6x1, R/A, TH"
  rect 1.55x1.55 hole 1.02: 1(0,6.35)
  round 1.55 hole 1.02: 2(0,3.81) 3(0,1.27) 4(0,-1.27) 5(0,-3.81) 6(0,-6.35)
  silkscreen extent 1.21,-7.87 10.11,7.87, body extent -0.2,-7.87 10.11,7.87, height 2.54
superSOT-6 [mm] "SOP, 6-Leads, Body 1.6x2.9mm, Pitch 0.95mm"
  rect 1x0.7 smd: 1(-1.3,0.95) 2(-1.3,0) 3(-1.3,-0.95) 4(1.3,-0.95) 5(1.3,0) 6(1.3,0.95)
  silkscreen extent -0.5,-1.5 0.5,1.7, body extent -1.5,-1.5 1.5,1.5, height 1.1
Switchcraft_RASM712PX [mm] "SWITCHCRAFT"
  round 1.524 hole 1.78 unplated: 0(0,3)
  rect 3.3x4.06 smd: 1(0.76,15.9)
  rect 3.3x6.35 smd: 2(6.86,6.76)
  rect 3.81x6.35 smd: 3(-6.43,6.76)
  silkscreen extent -4.62,0.62 4.57,14.72, body extent -4.57,0 4.58,14.73, height 11.18
TDK_B78416A2232A003 [mm] "SMT, 5-Leads, Body 8.8x7.6mm"
  rect 2.5x1.2 smd: 1(-3.35,2.2) 2(-3.35,0) 3(-3.35,-2.2) 4(3.35,-2.2) 6(3.35,2.2)
  silkscreen extent -4.3,-3.8 3.9,3.8, body extent -4.5,-3.8 4.5,3.8, height 7.1
Testpoint_Keystone_Miniature [mil] "Miniature SMT test point"
  rect 135x70 smd: 1(0,0)
  silkscreen extent -78,-46 78,45, body extent -52,-20 52,20, height 61
TI_Stacked_Overlay_Small [mil]
  silkscreen extent -418,-98 418,98
TI_Symbol_Overlay_Small [mil]
  silkscreen extent -90,-88 91,88
TSSOP-8 [mm] "TSSOP, 8-Leads, Body 3.1x4.5mm (max), Pitch 0.65mm, IPC Medium Density"
  rrect50% 1.7x0.35 smd: 1(-2.85,0.975) 2(-2.85,0.325) 3(-2.85,-0.325) 4(-2.85,-0.975) 5(2.85,-0.975) 6(2.85,-0.325) 7(2.85,0.325) 8(2.85,0.975)
  silkscreen extent -2.97,-1.55 1.6,1.83, body extent -3.2,-1.55 3.2,1.55, height 1.07
Wurth_60900213421 [mil] "Shunt, 2.54mm, Black"
  round 1 on Mech3: 0(0,0)
  body extent -98,-48 98,48, height 236

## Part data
C1: "CAP, CERM, 0.47 µF, 50 V, +/- 10%, X5R, 0603"
C2: "CAP, CERM, 2.2 µF, 50 V, +/- 10%, X7R, 1206"
C3: "CAP, CERM, 22 µF, 10 V, +/- 10%, X5R, 1206"
C4: "CAP, CERM, 10 µF, 16 V, +/- 10%, X5R, 0805"
C5: "CAP, CERM, 4.7 µF, 10 V, +/- 20%, X5R, 0603"
C6: "CAP, CERM, 1000 pF, 50 V, +/- 10%, X7R, 0805"
C7 C8 C9 C12 C13 C16: "CAP, CERM, 0.1 µF, 50 V, +/- 10%, X7R, 0603"
C10: "CAP, CERM, 390 pF, 100 V, +/- 5%, C0G/NP0, 0603"
C11: "CAP, CERM, 0.033 µF, 50 V, +/- 10%, X7R, 0603"
C14: "CAP, CERM, 220 pF, 50 V, +/- 10%, X7R, 0603"
C15: "CAP, CERM, 1500 pF, 100 V, +/- 5%, C0G/NP0, 0805"
C17: "CAP, AL, 100 µF, 35 V, +/- 20%, SMD"
D1: "Diode, Schottky, 60 V, 2 A, SMB"
D2 D10: "Diode, TVS, Uni, 27 V, 40 W, SOT-23"
D3 D4: "Diode, Schottky, 30 V, 1 A, SOD-323F"
D5: "Diode, Schottky, 60 V, 1 A, SOD-123F"
D6: "LED, Orange, SMD"
D7 D8 D9: "LED, Red, SMD"
D11 D12: "Diode, Switching, 350 V, 0.225 A, SOD-123"
FID1 FID2 FID3 FID4 FID5 FID6: "Fiducial mark.  There is nothing to buy or mount."
J1/J3: library part BoosterPack_40pin_J1J3, "Receptacle, 2.54mm, 10x2, Tin, TH"
J2/J4: library part BoosterPack_40pin_J2J4, "Receptacle, 2.54mm, 10x2, Tin, TH"
J5: "Power Jack, 2.5mm, R/A, SMT"
J6: "Header, 2.54 mm, 3x1, Tin, TH"
J7: "Header, 2.54mm, 2x2, Gold, SMT"
J8: "Receptacle, 2.54mm, 6x1, Gold, R/A, Black, TH"
J9 J11 J12 J14: "Header, 100mil, 2x1, Tin, TH"
J10 J13: "Header, 2.54mm, 6x1, Gold, TH"
L1: "Inductor, Shielded Drum Core, Ferrite, 10 µH, 1.15 A, 0.16 ohm, SMD"
L2: "Inductor, Drum Core, Ferrite, 10 µH, 1.15 A, 0.18 ohm, SMD"
Logo1 Logo4 Logo5: library part TI_Logo, "Texas Instrument Corporate Signature"
Logo2: library part Pb-Free
Logo3: library part FCC_disclaimer, "FCC_disclaimer"
Q1: "MOSFET, N-CH, 60 V, 0.115 A, SOT-363"
Q2: "MOSFET, P-CH, -30 V, -1.8 A, superSOT-6"
Q3: "MOSFET, N-CH, 100 V, 0.17 A, SOT-23"
R1: "RES, 10, 5%, 0.75 W, 2010"
R2: "RES, 100 k, 1%, 0.063 W, 0402"
R3: "RES, 2.2 M, 1%, 0.25 W, 1206"
R4: "RES, 383 k, 1%, 0.063 W, 0402"
R5: "RES, 33, 5%, 0.75 W, AEC-Q200 Grade 0, 2010"
R6: "RES, 51.1 k, 1%, 0.063 W, 0402"
R7 R9 R18: "RES, 10.0 k, 1%, 0.063 W, 0402"
R8: "RES, 51 k, 5%, 0.1 W, 0603"
R10: "RES, 10 k, 5%, 0.1 W, 0603"
R11 R12 R14 R16: "RES, 0, 5%, 0.063 W, 0402"
R13: "RES, 100 k, 5%, 0.063 W, 0402"
R15 R17 R32 R34 R35 R36 R39 R40: "RES, 0, 5%, 0.25 W, 1206"
R19 R21 R25 R28 R29 R30 R31: "RES, 1.0 k, 5%, 0.1 W, 0603"
R20: "RES, 1.0 k, 5%, 0.75 W, AEC-Q200 Grade 0, 2010"
R22 R23 R24 R26 R27: "RES, 100 k, 5%, 0.1 W, 0603"
R33: "RES, 2.0 k, 5%, 0.063 W, 0402"
R37: "RES, 100, 5%, 0.125 W, 0805"
R38: "RES, 2.7 k, 5%, 0.25 W, 1206"
R41: "RES, 100, 1%, 0.1 W, 0603"
SH-J1: "Shunt, 2.54mm, Gold, Black"
T1: "Transformer, 3 mH, SMT"
TP1 TP2 TP3 TP4 TP5: library part 5015, "Test Point, Miniature, SMT"
U1: "28V, 0.5A Step-Down Converter with Sleep Mode, DQC0010A"
U2: "SIMPLE SWITCHER 24Vout, 2.1A Step-Up Voltage Regulator in SOT-23, DBV0005A"
U3: "PGA460TPWRQ1, PW0016A"
U4: "16-BIT TO 8-BIT MULTIPLEXER/DEMULTIPLEXER GIGABIT ETHERNET LAN SWITCH WITH POWER DOWN MODE, RUA0042A"
U5: "Dual Comparator, PW0008A"
U6: "512Kbit SPI Serial SRAM with SDI and SQI Interface,"
U7: "Ultrasonic Transducer, 6 VPP, 40 kHz, 4500 pF, -20 to 60 degC, SMD, 4-Pin Body 5.2 x 5.2 mm"
ZZ1 ZZ2 ZZ3 ZZ4 ZZ5: library part AssemblyNote

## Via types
v1: diameter 32, hole 12, Top Layer to Bottom Layer, tented both sides, 125 vias
v2: diameter 50, hole 28, Top Layer to Bottom Layer, 28 vias
v3: diameter 19.68, hole 7.87, Top Layer to Bottom Layer, tented both sides, 14 vias
v4: diameter 80, hole 55, Top Layer to Bottom Layer, 12 vias

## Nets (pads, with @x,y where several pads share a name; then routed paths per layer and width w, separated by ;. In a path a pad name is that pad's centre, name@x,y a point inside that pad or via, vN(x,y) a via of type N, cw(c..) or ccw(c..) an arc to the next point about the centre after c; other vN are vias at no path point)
3V3LP: J1/J3.1 R13.2 R19.1 R21.2 R25.2 R26.1 U4.39 U6.8 | length 3732.6
  Top Layer w10: 1178,1050 1178.53,1049.47 U4.39@1178.53,992.18 ; U6.8@1408.39,600.8 1408.39,645.39 1449.5,686.5 R25.2@1449.5,922 ; v1(1566,1160) 1599.5,1160
  Top Layer w20: J1/J3.1@260,1100 J1/J3.1@250,1100 ; R13.2@749.38,202 647,202 590,145 209,145 144,210 144,994 J1/J3.1@250,1100 ; R25.2@1449,922.5 1416.5,922.5 R26.1@1385,954 1372,954 1276,1050 1178,1050 300,1050 J1/J3.1@250,1100 ; R19.1@1601,1127.5 R21.2@1601,1195.5
  Bottom Layer w10: v1(1284,1069) 1548,1069 1566,1087 v1(1566,1160)
5VLP: D3.1 J1/J3.21 J7.3 | length 1964
  Top Layer w10: J7.3@1072,1576 J7.3@1072,1617.6
  Top Layer w30: v2@1667,1480 1710.51,1480
  Top Layer w50: J1/J3.21@350,1100 383,1133 v2(757,1133) ; J7.3@1072,1576 v2(1136,1512)
  Bottom Layer w40: 989,1342 1008.87,1322.13 1644.13,1322.13 1667,1345 v2(1667,1481)
  Bottom Layer w50: v2(757,1133) v2(1136,1512)
AVDD: C7.1 U3.16 | length 59.8
  Top Layer w10: C7.1@944.5,494 U3.16@1004.29,494
COM_PD: J2/J4.18 U4.5 | length 2335.9
  Top Layer w10: v1(926,883) 933,883 940.13,890.13 1047.59,890.13 1052.2,894.74 U4.5@1081.09,894.74
  Bottom Layer w10: v1(926,883) 908.13,865.13 908.13,822.04 1396.04,334.13 1400.87,334.13 1486,249 2083,249 2120,286 2120,830 J2/J4.18@2050,900
COM_SEL: J2/J4.17 U4.13 | length 2108.4
  Top Layer w10: v1@1021.49,647.51 1025,651.01 v1(1025,656) 1025,686.72 1051.48,713.2 1051.48,725.35 1062.48,736.35 1080.18,736.35 U4.13@1081.09,737.26 ; J2/J4.17@2050,800 2151,699 v1(2151,692)
  Bottom Layer w10: v1@1021.49,647.51 1046.13,647.51 1541.63,152 2086,152 2140,206 v1@2140,693.64
DECPL: J8.6 R11.1 R12.1 U3.13 | length 708.3
  Top Layer w10: R11.1@796.62,335 R12.1@796.62,382 ; R12.1@805,384 814,393 1040.72,393 1081.2,433.48 U3.13@1081.2,494.14 ; v1(843,292) 843,391 845,393
  Bottom Layer w10: v1(843,292) 843,145 J8.6@882,106
DECPL_A: J1/J3.2 R12.2 | length 973.9
  Top Layer w10: R12.2@749.38,382 749.38,400.38 v1(773,424)
  Bottom Layer w10: J1/J3.2@250,1000 300,950 381,950 418,913 418,639 633,424 v1(773,424)
DECPL_D: J1/J3.5 R11.2 | length 916.3
  Top Layer w10: v1(555,286) 604,335 R11.2@749.38,335
  Bottom Layer w10: J1/J3.5@250,700 236,700 189,653 189,477 216,450 391,450 v1(555,286)
DECPL_DD: J10.1
DECPL_XD: J13.1 Q3.1 | length 463.9
  Bottom Layer w10: J13.1@107.05,2107 366,2107 470.76,2211.76 Q3.1@470.76,2268.6
DS1_LED: D9.1 J2/J4.38 | length 608.7
  Top Layer w10: J2/J4.38@1950,900 1883,967 1883,1180.47 D9.1@2095.5,1392.97
F_DIAG_LED: D8.1 J2/J4.39 | length 422.9
  Top Layer w10: J2/J4.39@1950,1000 1903.29,1046.71 1903.29,1131.82 D8.1@2095.47,1324
GND: C1.2 C2.2 C3.2 C4.2 C5.2 C7.2 C8.2 C9.2 C11.2 C12.2 C14.2 D2.2 D6.2 D10.2 J1/J3.22 J2/J4.20 J5.2 J5.3 J6.3 J8.2 Q1.1 Q1.4 R4.2 R9.2 R10.2 R17.1 R18.2 R23.1 R27.1 U1.1 U1.4 U1.6 U1.11 U2.2 U3.1 U3.4 U4.43 U5.4 U6.4 | length 356.5
  Top Layer w10: U3.4@1081.2,261.86 U3.4@1083.49,264.14 ; R17.1@1248.09,487.09 R17.1@1261,487.09 ; R18.2@1267,835.62 v1@1302.62,835.62 ; v1(1303,836) 1331.61,836 U6.4@1331.61,825.2 ; v1(1557,911) 1568,911 1582.6,925.6 Q1.4@1583.41,925.6 ; Q1.1@1634.59,1000.4 1634.59,1033 v1(1650,1033) ; U1.4@1753.6,1680.32 1782.81,1680.32 U1.11@1782.81,1691.81 ; U1.1@1753.6,1739.37 1791,1739.37 U1.11@1791,1700 v3(1791,1683.62) 1791,1676.69 1807.06,1660.63 U1.6@1828.4,1660.63
  other v1: 108,166 1208,166 1408,166 892,248 1102,315 1077,339 658,466 608,566 808,566 458,666 558,666 658,666 1558,666 1758,666 1858,666 508,766 608,766 708,766 1508,766 1808,766 458,866 558,866 658,866 1758,866 1858,866 2158,866 1808,966 2108,966 158,1066 1758,1066 2158,1066 1207,1086 1097,1087 108,1166 208,1166 308,1166 1808,1166 2108,1166 758,1266 1058,1266 1158,1266 1758,1266 1858,1266 108,1366 508,1366 1808,1366 1908,1366 2008,1366 158,1466 758,1466 858,1466 958,1466 1958,1466 2058,1466 108,1566 208,1566 308,1566 408,1566 508,1566 2008,1566 2108,1566 358,1666 1158,1666 2158,1666 308,1766 408,1766 2108,1766 758,1866 1258,1866 1758,1866 1858,1866 1958,1866 2058,1866 2158,1866
  other v2: 221,1628.5 505,1627.5 505,1680.25 221,1681.25 505,1733 221,1734 505,1785.75 221,1786.75 505,1838.5 221,1839.5
  other v3: 1149,677.22 1121.44,723.48 1176.56,723.48 1121.44,769.74 1176.56,769.74 1121.44,816 1176.56,816 1121.44,862.26 1176.56,862.26 1121.44,908.52 1176.56,908.52 1149,954.78 1791,1716.38
GND_DD: J10.5 J11.2 R35.1
  other v1: 1358,2166 1408,2266 1508,2266 1608,2266 1258,2366 1358,2366 1458,2366 2108,2466 1858,2566 2058,2566
  other v4: 1262,2109 1262,2197 1262,2285
GND_XD: C16.1 C17.2 J12.2 J13.5 J14.2 Q3.2 R38.1 R39.1 R40.1
  other v1: 408,2266 1058,2366 208,2466 358,2566 658,2566 758,2566
  other v4: 1052,2434 1052,2522 1052,2610
GNDP: C13.2 R17.2 U3.6 | length 526.2
  Top Layer w10: U3.6@1132.39,261.86 1132.39,298.39 1144,310 ; C13.2@1242,299.5 C13.2@1242,310 ; R17.2@1242,353.91 R17.2@1261,372.91 ; 1144,310 C13.2@1242,310 ; 1144,310 C13.2@1242,310 ; 1144,310 C13.2@1242,310 ; 1144,310 C13.2@1242,310
  Top Layer w30: C13.2@1242,310 R17.2@1242,353.91
INN: C11.1 U3.3 | length 159.9
  Top Layer w10: 1034.5,324.5 1055.61,303.39 U3.3@1055.61,261.86
  Top Layer w30: C11.1@946,324.5 1034.5,324.5
INP: C10.1 U3.2 | length 81.1
  Top Layer w17: U3.2@1030.02,261.86 1030.02,226.98 1049.99,207.01 C10.1@1049.99,189
INP_DD: J10.2 J11.1 R32.2 | length 777
  Top Layer w20: J11.1@1512,2151 1573,2090 2037,2090 2064,2117 2064,2152 2127,2215 2179.57,2215 J10.2@2187.95,2206.63
INP_XD: J13.2 J14.1 R36.2 | length 1747.7
  Top Layer w30: J13.2@116.5,2208.5 167,2158 979,2158 991,2170 ; R36.2@795.08,2354.93 896,2455.85 896,2610 J14.1@898,2612 ; 896,2472 991,2377 991,2197 ; 993,2285 v4(1052,2285) ; v4(1052,2109) 991,2170 ; v4(1052,2197) 991,2197 ; 991,2170 991,2197
IO: C12.1 C14.1 D10.1 D12.2 J6.2 R15.1 R20.1 R22.2 | length 2320.1
  Top Layer w10: R15.1@1340.25,348.07 1347.32,341 R15.1@1359,341 ; 1413.5,369.65 D10.1@1424.76,358.4
  Top Layer w30: R15.1@1359,341 1387.65,369.65 1446.65,369.65 1470.5,393.5 1470.5,566.5 1493,589 R20.1@1501,589 ; R20.1@1481.95,639.73 1481.95,670.95 1586,775 1672,775 1706.75,809.75 1706.75,1256.25 1640,1323 R22.2@1593.5,1323 ; R22.2@1594.99,1331 1594.99,1380.99 v2(1603,1389)
  Bottom Layer w10: v2(1603,1389) 1603,1376 v2@1608,1371
  Bottom Layer w30: J6.2@810,1761 821,1750 1242,1750 v2@1608,1384
IO_460: C13.1 R15.2 TP4.1 U3.8 | length 437.3
  Top Layer w10: U3.8@1183.57,261.86 1183.57,248.43 1187,245 1217,245 ; R15.2@1356,232.91 R15.2@1366.91,222 ; TP4.1@1521,113 TP4.1@1543,113
  Top Layer w20: R15.2@1356,232.91 1401.09,232.91 TP4.1@1521,113
  Top Layer w30: 1213,245 1217,245 R15.2@1349.91,245
IOREG: C9.1 U3.14 | length 560.1
  Top Layer w10: U3.14@1055.61,494.14 1055.61,438.61 1040,423 ; C9.1@943.5,423 1040,423 ; C9.1@943.5,423 1040,423 ; C9.1@943.5,423 1040,423 ; C9.1@943.5,423 1040,423 ; C9.1@943.5,423 1040,423
MAIN: C1.1 D1.2 D4.1 D11.2 J5.1 J6.1 J7.1 R24.2 | length 2328.8
  Top Layer w10: D4.1@1177.76,1389 1166,1389 1143,1366 1173,1366 D4.1@1184,1377
  Top Layer w30: v2@1571.53,838.47 D11.2@1627,838.47
  Top Layer w50: C1.1@215.5,1355 J5.1@316.06,1355 ; J5.1@344.03,1399.03 374,1429 550,1429 653,1532 849.58,1532 ; 814,1541 J6.1@814,1649 ; 858.57,1529.43 979.57,1529.43 1143,1366 v2(1242,1267) 1242,1291 1276,1325 R24.2@1356.5,1325
  Bottom Layer w30: v2@1234,1270 1242.86,1261.14 1530.86,1261.14 1609,1183 1609,881 v2(1569,841)
MAIN_LOCAL: C2.1 J7.2 U1.2 U1.3 | length 970.8
  Top Layer w10: U1.3@1753.6,1700 1754.6,1709.69
  Top Layer w20: J7.2@972,1792.4 972,1845 1041,1914 1541,1914 1548,1907 1607,1848 1607,1779 1667.9,1718.1 C2.1@1678,1718.1 ; C2.1@1702.24,1709.69 1754.6,1709.69
MEM_CS: J2/J4.37 U6.1 | length 662.2
  Top Layer w10: v1(1411,730) U6.1@1411,822.59
  Bottom Layer w10: v1(1411,730) 1876,730 1905,759 1907,757 J2/J4.37@1950,800
MEM_HOLD: J2/J4.36 U6.7 | length 714.1
  Top Layer w10: v1@1382.8,540.8 U6.7@1382.8,600.8 ; J2/J4.36@1950,683 J2/J4.36@1950,700
  Bottom Layer w10: v1(1380,538) 1788,538 J2/J4.36@1950,700
MEM_MISO: U4.25 U6.2 | length 267.4
  Top Layer w10: U4.25@1216.91,717.57 1217.82,716.67 1246.7,716.67 1270.37,693 1313,693 1382.8,762.8 U6.2@1382.8,825.2
MEM_MOSI: U4.24 U4.26 U6.5 | length 386.2
  Top Layer w10: U4.24@1216.91,697.89 1240.21,697.89 1267,671.1 1315.9,671.1 1323.76,663.24 ; U4.26@1216.91,737.26 1277.74,737.26 v1(1292,723) ; v1(1300,641) 1301.52,641 1323.76,663.24 ; U6.5@1331.61,600.8 1331.61,655.39 1323.76,663.24
  Bottom Layer w10: v1(1292,723) 1300,715 v1(1300,641)
MISO_LP: J1/J3.9 U4.11 | length 1061.6
  Top Layer w10: J1/J3.9@250,300 299.6,349.6 443.66,349.6 713.06,619 951,619 978.25,646.25 978.25,702.68 1051.3,775.72 1080.18,775.72 U4.11@1081.09,776.63
MOSI_LP: J1/J3.10 U4.12 | length 1095.9
  Top Layer w10: J1/J3.10@250,200 301,251 377,251 726,600 959.07,600 996.13,637.06 996.13,695.28 1056.89,756.04 1080.18,756.04 U4.12@1081.09,756.94
NetC3_1: C3.1 D3.2 L1.2 R2.1 R3.2 U1.8 U1.10 | length 881.6
  Top Layer w10: R3.2@1783.09,1576 R3.2@1793.71,1565.38 ; U1.8@1828.4,1700 1856,1700 1867,1689 ; U1.10@1828.4,1739.37 1828.4,1756.4 ; C3.1@1866.07,1483 C3.1@1871,1487.93
  Top Layer w20: 1828.4,1756.4 1854,1782 v2(1854,1800) ; 1867,1689 1925,1689
  Top Layer w30: R3.2@1793.71,1565.38 1871,1565.38 ; D3.2@1816.24,1483 C3.1@1866.07,1483 ; C3.1@1871,1487.93 1871,1565.38 ; 1925,1684 1925,1582.96 1907.42,1565.38 1871,1565.38 ; v2(1954,1587) 1954,1622 1950,1626 L1.2@1976,1652
  Bottom Layer w30: v2(1854,1800) 1854,1718 1851,1715 1950.62,1615.38 v2@1950.62,1599.56
NetC4_1: C4.1 C6.1 D4.2 D5.1 R6.2 | length 536.3
  Top Layer w10: C6.1@1425,1514 C6.1@1426,1513 ; R6.2@1575,1485 R6.2@1575,1493.38
  Top Layer w20: 1424,1458 1548,1458 R6.2@1575,1485
  Top Layer w30: D4.2@1273.24,1391 1417,1391 1426,1400 C6.1@1426,1513 ; D5.1@1330.12,1484 C6.1@1425,1484
NetC5_1: C5.1 L2.1 R5.2 R7.1 U2.5 | length 239.6
  Top Layer w10: R7.1@1450.38,1756 R7.1@1456.5,1762.13
  Top Layer w30: L2.1@1290.96,1710 1427.73,1710 1419.87,1717.87
  Top Layer w50: 1442,1734 C5.1@1442,1817
NetC6_2: C6.2 R6.1 R9.1 U2.3 | length 190.4
  Top Layer w10: C6.2@1505,1514 C6.2@1511.4,1520.4
  Top Layer w20: C6.2@1511.4,1520.4 1511.4,1592.87 1568,1592.87 R6.1@1568,1540.62
NetC10_2: C10.2 R41.2 | length 56
  Top Layer w30: R41.2@938.5,189 C10.2@994.5,189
